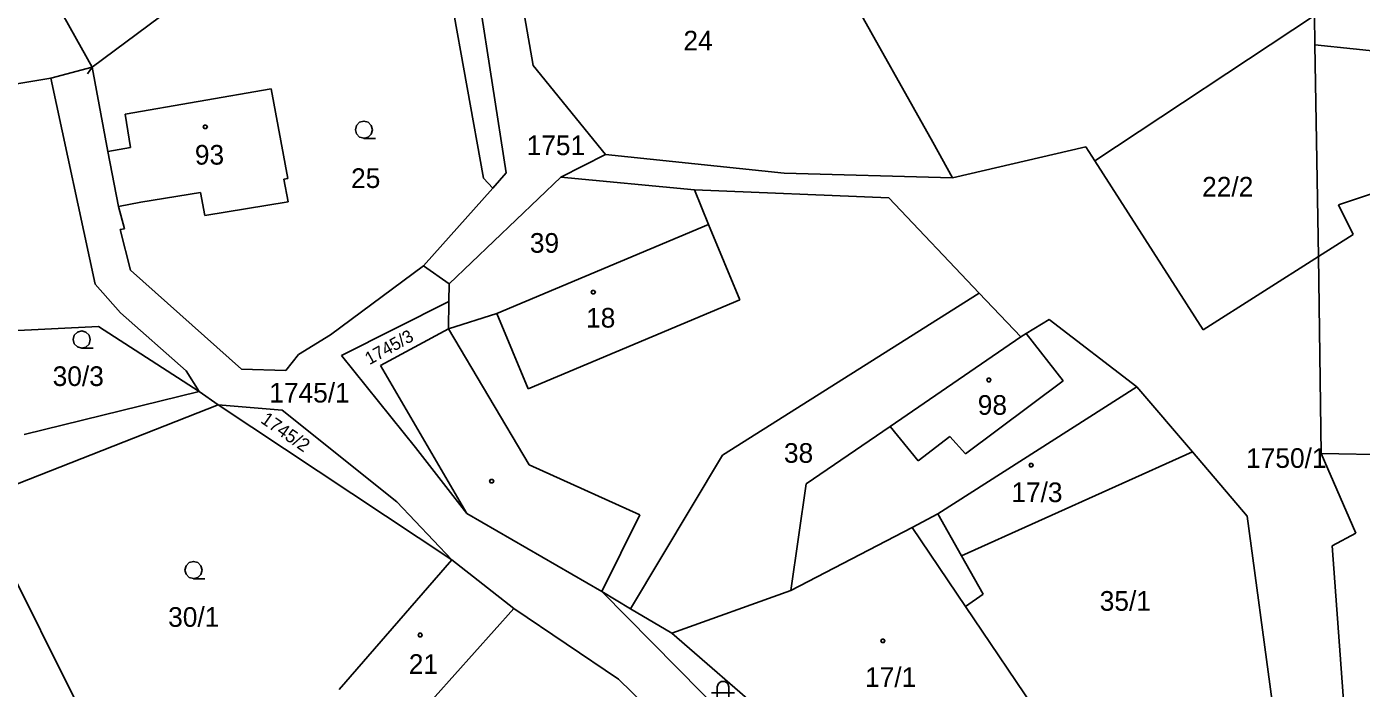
# Model space of a CAD drawing. Extents: x -799786 to -795190, y -1021716 to -1017834.
# Drawn here: x -798163.2 to -798047.9, y -1019081.9 to -1019024.7 of the extents above; entities that cross this region are included whole.
import ezdxf

# ---------------------------------------------------------------- set-up
doc = ezdxf.new("R2010")
doc.units = 0
for name, color, linetype in [('Default', 7, 'Continuous'), ('KN_HRANICE', 7, 'Continuous'), ('KN_KULTURY', 7, 'Continuous'), ('KN_PARCELY', 7, 'Continuous'), ('KN_SLUCKY', 7, 'Continuous')]:
    doc.layers.add(name, color=color, linetype=linetype)

# ---------------------------------------------------------------- blocks, each defined once
blk = doc.blocks.new('304')
at = {"layer": 'Default'}
blk.add_lwpolyline([(0, 0), (-0.38, 0.1), (-0.65, 0.37), (-0.75, 0.74), (-0.65, 1.11), (-0.38, 1.38), (-0.01, 1.48), (0.36, 1.38), (0.63, 1.11), (0.73, 0.73), (0.63, 0.35), (0.36, 0.08), (-0.02, -0.02), (0.98, -0.02)], dxfattribs=at)
blk = doc.blocks.new('316')
at = {"layer": 'Default'}
for points in [[(-0.5, 1.5), (-0.4, 1.79), (-0.15, 1.97), (0.16, 1.97), (0.41, 1.79), (0.51, 1.5), (0.51, 0.5), (0.41, 0.21), (0.16, 0.03), (-0.15, 0.03), (-0.4, 0.21), (-0.5, 0.5), (-0.5, 1.5)], [(-1, 1), (0.27, 1), (1, 1)]]:
    blk.add_lwpolyline(points, dxfattribs=at)
blk = doc.blocks.new('NAHRADNI_SYMBOL')
at = {"layer": 'Default'}
blk.add_lwpolyline([(0.09, 0.15), (0.18, 0), (0.09, -0.15), (-0.09, -0.15), (-0.18, 0), (-0.09, 0.15), (0.09, 0.15)], dxfattribs=at)
blk = doc.blocks.new('402')
at = {"layer": 'Default'}
blk.add_lwpolyline([(0.09, 0.15), (0.18, 0), (0.09, -0.15), (-0.09, -0.15), (-0.18, 0), (-0.09, 0.15), (0.09, 0.15)], dxfattribs=at)
blk = doc.blocks.new('4201')
at = {"layer": 'Default'}
blk.add_line((0, 0), (-0.5, -0.5), dxfattribs=at)

msp = doc.modelspace()

# ---------------------------------------------------------------- linework, layer by layer
at = {"layer": 'KN_HRANICE'}
for p, q in [((-798123.74, -1019037.77), (-798129.28, -1019007.09)), ((-798121.26, -1019017.53), (-798119.44, -1019028.03)), ((-798121.77, -1019037.3), (-798124.46, -1019020.04)), ((-798092.37, -1019021.37), (-798084.9, -1019034.66)), ((-798157.55, -1019028.18), (-798151.73, -1019023.84)), ((-798070.91, -1019036.26), (-798051.93, -1019023.72)), ((-798051.89, -1019026.25), (-798051.93, -1019023.72)), ((-798051.89, -1019026.25), (-798020.73, -1019029.44)), ((-798051.56, -1019044.54), (-798051.89, -1019026.25)), ((-798157.55, -1019028.18), (-798161.12, -1019029.12)), ((-798157.55, -1019028.18), (-798156.19, -1019035.46)), ((-798119.44, -1019028.03), (-798113.2, -1019035.72)), ((-798178.49, -1019032.04), (-798161.12, -1019029.12)), ((-798161.12, -1019029.12), (-798157.31, -1019046.95)), ((-798154.71, -1019032.24), (-798142.09, -1019030.04)), ((-798142.09, -1019030.04), (-798140.64, -1019037.8)), ((-798154.25, -1019035.11), (-798154.71, -1019032.24)), ((-798084.9, -1019034.66), (-798083.19, -1019037.75)), ((-798156.19, -1019035.46), (-798154.25, -1019035.11)), ((-798156.19, -1019035.46), (-798155.29, -1019040.21)), ((-798117.04, -1019037.69), (-798113.2, -1019035.72)), ((-798113.2, -1019035.72), (-798097.75, -1019037.34)), ((-798083.19, -1019037.75), (-798071.68, -1019035.07)), ((-798071.68, -1019035.07), (-798070.91, -1019036.26)), ((-798061.54, -1019050.89), (-798070.91, -1019036.26)), ((-798140.98, -1019037.86), (-798140.64, -1019037.8)), ((-798140.61, -1019039.83), (-798140.98, -1019037.86)), ((-798126.69, -1019046.9), (-798117.04, -1019037.69)), ((-798122.94, -1019038.64), (-798123.74, -1019037.77)), ((-798122.94, -1019038.64), (-798121.77, -1019037.3)), ((-798105.51, -1019038.78), (-798117.04, -1019037.69)), ((-798097.75, -1019037.34), (-798083.19, -1019037.75)), ((-798043.3, -1019037.91), (-798049.84, -1019040.07)), ((-798148.19, -1019039.02), (-798153.36, -1019039.86)), ((-798147.82, -1019040.99), (-798148.19, -1019039.02)), ((-798128.93, -1019045.35), (-798122.94, -1019038.64)), ((-798105.51, -1019038.78), (-798104.28, -1019041.78)), ((-798105.51, -1019038.78), (-798088.72, -1019039.48)), ((-798153.36, -1019039.86), (-798155.29, -1019040.21)), ((-798155.29, -1019040.21), (-798154.76, -1019042.14)), ((-798140.61, -1019039.83), (-798147.82, -1019040.99)), ((-798088.72, -1019039.48), (-798080.9, -1019047.7)), ((-798049.84, -1019040.07), (-798048.59, -1019042.65)), ((-798154.76, -1019042.14), (-798155.13, -1019042.2)), ((-798155.13, -1019042.2), (-798154.25, -1019045.73)), ((-798104.28, -1019041.78), (-798122.57, -1019049.48)), ((-798048.59, -1019042.65), (-798051.56, -1019044.54)), ((-798051.56, -1019044.54), (-798061.54, -1019050.89)), ((-798051.33, -1019061.57), (-798051.56, -1019044.54)), ((-798154.25, -1019045.73), (-798144.65, -1019054.27)), ((-798136.96, -1019051.31), (-798128.93, -1019045.35)), ((-798126.69, -1019046.9), (-798128.93, -1019045.35)), ((-798157.31, -1019046.95), (-798155.11, -1019049.42)), ((-798126.69, -1019046.9), (-798126.73, -1019048.42)), ((-798126.73, -1019048.42), (-798136.01, -1019053.1)), ((-798126.73, -1019048.42), (-798126.76, -1019050.8)), ((-798103.08, -1019061.72), (-798080.9, -1019047.7)), ((-798080.9, -1019047.7), (-798077.29, -1019051.49)), ((-798155.11, -1019049.42), (-798149.42, -1019054.42)), ((-798122.57, -1019049.48), (-798126.76, -1019050.8)), ((-798157.02, -1019050.59), (-798165.14, -1019051)), ((-798148.3, -1019056.22), (-798157.02, -1019050.59)), ((-798132.63, -1019053.96), (-798126.76, -1019050.8)), ((-798076.85, -1019051.19), (-798074.85, -1019049.99)), ((-798074.85, -1019049.99), (-798067.28, -1019055.8)), ((-798139.71, -1019053.03), (-798136.96, -1019051.31)), ((-798088.59, -1019059.23), (-798077.29, -1019051.49)), ((-798077.29, -1019051.49), (-798076.85, -1019051.19)), ((-798140.81, -1019054.41), (-798139.71, -1019053.03)), ((-798136.01, -1019053.1), (-798129.61, -1019061.05)), ((-798144.65, -1019054.27), (-798140.81, -1019054.41)), ((-798125.18, -1019066.77), (-798132.63, -1019053.96)), ((-798149.42, -1019054.42), (-798148.3, -1019056.22)), ((-798163.44, -1019059.94), (-798148.3, -1019056.22)), ((-798146.66, -1019057.36), (-798148.3, -1019056.22)), ((-798067.28, -1019055.8), (-798084.47, -1019066.8)), ((-798067.28, -1019055.8), (-798062.46, -1019061.44)), ((-798167.64, -1019065.62), (-798146.66, -1019057.36)), ((-798146.66, -1019057.36), (-798126.47, -1019070.78)), ((-798095.85, -1019064.2), (-798088.59, -1019059.23)), ((-798129.61, -1019061.05), (-798125.18, -1019066.77)), ((-798103.08, -1019061.72), (-798111.02, -1019075)), ((-798062.46, -1019061.44), (-798082.43, -1019070.41)), ((-798062.46, -1019061.44), (-798057.73, -1019066.99)), ((-798035.14, -1019061.9), (-798051.33, -1019061.57)), ((-798051.33, -1019061.57), (-798048.35, -1019068.47)), ((-798097.17, -1019073.42), (-798095.85, -1019064.2)), ((-798167.64, -1019065.62), (-798151.06, -1019098.77)), ((-798113.52, -1019073.52), (-798125.18, -1019066.77)), ((-798084.47, -1019066.8), (-798086.68, -1019067.96)), ((-798057.73, -1019066.99), (-798055.57, -1019083.01)), ((-798086.68, -1019067.96), (-798097.17, -1019073.42)), ((-798086.68, -1019067.96), (-798082.07, -1019074.8)), ((-798048.35, -1019068.47), (-798050.39, -1019069.57)), ((-798082.43, -1019070.41), (-798080.55, -1019073.74)), ((-798050.39, -1019069.57), (-798048.79, -1019091.15)), ((-798136.2, -1019081.97), (-798126.47, -1019070.78)), ((-798126.47, -1019070.78), (-798121.12, -1019074.97)), ((-798113.52, -1019073.52), (-798111.02, -1019075)), ((-798113.52, -1019073.52), (-798100.81, -1019086.36)), ((-798107.46, -1019077.11), (-798097.17, -1019073.42)), ((-798080.55, -1019073.74), (-798082.07, -1019074.8)), ((-798121.12, -1019074.97), (-798112.06, -1019081.09)), ((-798111.02, -1019075), (-798107.46, -1019077.11)), ((-798082.07, -1019074.8), (-798074.93, -1019085.38)), ((-798107.46, -1019077.11), (-798097.74, -1019085.52)), ((-798112.06, -1019081.09), (-798107.47, -1019085.54))]:
    msp.add_line(p, q, dxfattribs=at)
msp.add_lwpolyline([(-798146.66, -1019057.36), (-798141.14, -1019057.82), (-798131.23, -1019065.74), (-798126.47, -1019070.78)], dxfattribs=at)
at = {"layer": 'KN_SLUCKY'}
for p, q in [((-798161.85, -1019020.48), (-798157.55, -1019028.18)), ((-798104.28, -1019041.78), (-798101.59, -1019048.28)), ((-798101.59, -1019048.28), (-798119.88, -1019055.98)), ((-798122.57, -1019049.48), (-798119.88, -1019055.98)), ((-798119.78, -1019062.55), (-798126.76, -1019050.8)), ((-798076.85, -1019051.19), (-798073.64, -1019055.28)), ((-798073.64, -1019055.28), (-798082.09, -1019061.6)), ((-798086.18, -1019062.21), (-798088.59, -1019059.23)), ((-798083.42, -1019060.11), (-798086.18, -1019062.21)), ((-798082.09, -1019061.6), (-798083.42, -1019060.11)), ((-798110.22, -1019066.89), (-798119.78, -1019062.55)), ((-798113.52, -1019073.52), (-798110.22, -1019066.89)), ((-798084.47, -1019066.8), (-798082.43, -1019070.41)), ((-798121.12, -1019074.97), (-798130.62, -1019085.59))]:
    msp.add_line(p, q, dxfattribs=at)

# ---------------------------------------------------------------- block references
at = {"layer": 'KN_KULTURY'}
for name, p in [('402', (-798147.78, -1019033.34)), ('304', (-798134.06, -1019034.32)), ('402', (-798114.25, -1019047.62)), ('304', (-798158.45, -1019052.46)), ('402', (-798080.06, -1019055.22)), ('402', (-798076.41, -1019062.58)), ('402', (-798123.03, -1019063.97)), ('304', (-798148.79, -1019072.39)), ('402', (-798129.21, -1019077.27)), ('NAHRADNI_SYMBOL', (-798089.22, -1019077.78)), ('316', (-798103.04, -1019083.26))]:
    msp.add_blockref(name, p, dxfattribs=at)
at = {"layer": 'KN_SLUCKY', "rotation": 8.651663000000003}
msp.add_blockref('4201', (-798157.55, -1019028.18), dxfattribs=at)

# ---------------------------------------------------------------- texts
at = {"layer": 'KN_PARCELY'}
for s, p in [('24', (-798106.46, -1019026.73)), ('1751', (-798120.01, -1019035.78)), ('93', (-798148.68, -1019036.6)), ('25', (-798135.18, -1019038.62)), ('22/2', (-798061.63, -1019039.36)), ('39', (-798119.73, -1019044.22)), ('18', (-798114.87, -1019050.69)), ('30/3', (-798160.97, -1019055.74)), ('1745/1', (-798142.25, -1019057.17)), ('98', (-798081.02, -1019058.23)), ('38', (-798097.77, -1019062.38)), ('1750/1', (-798057.83, -1019062.82)), ('17/3', (-798078.12, -1019065.78)), ('35/1', (-798070.48, -1019075.17)), ('30/1', (-798150.99, -1019076.56)), ('21', (-798130.19, -1019080.63)), ('17/1', (-798090.76, -1019081.76))]:
    msp.add_text(s, height=1.7, dxfattribs=at).set_placement(p)
for s, height, rotation, p in [('1745/3', 1.1, 29.049, (-798133.6, -1019053.95)), ('1745/2', 1.14, 325.211, (-798143.08, -1019058.85))]:
    msp.add_text(s, height=height, rotation=rotation, dxfattribs=at).set_placement(p)

doc.saveas('drawing.dxf')
